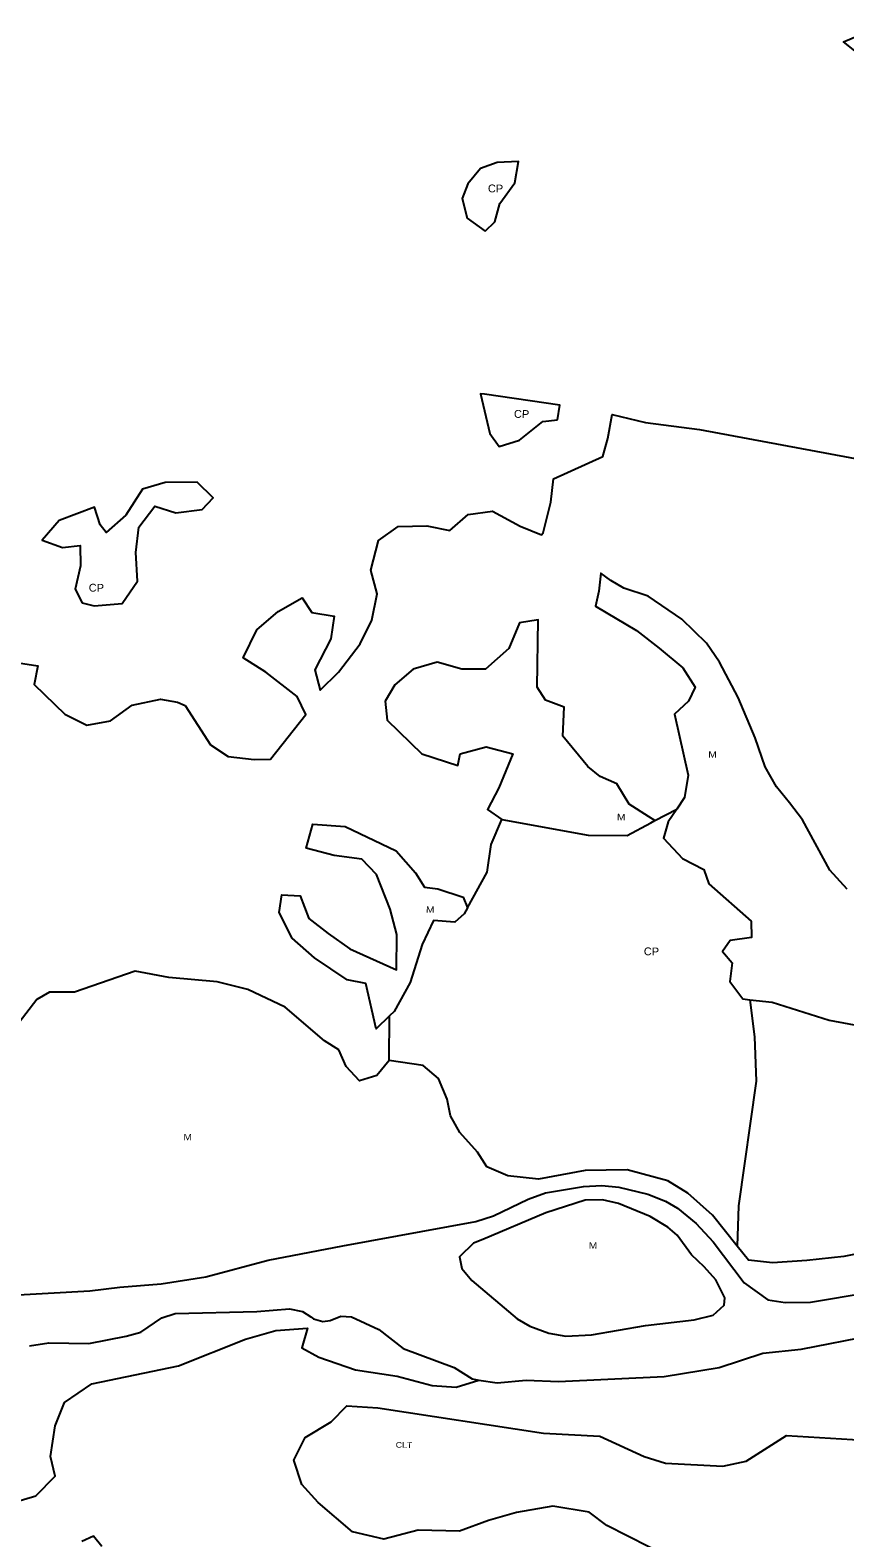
# Model space of a CAD drawing. Extents: x 713589 to 726391, y 7177764 to 7191819.
# Drawn here: x 714627 to 715293, y 7183555 to 7184788 of the extents above; entities that cross this region are included whole.
import ezdxf
from ezdxf.enums import TextEntityAlignment as Align

# ---------------------------------------------------------------- set-up
doc = ezdxf.new("R2010")
doc.units = 0
doc.header["$LTSCALE"] = 2.6
doc.layers.add('63', color=7, linetype='Continuous', lineweight=25)

msp = doc.modelspace()

# ---------------------------------------------------------------- linework, layer by layer
at = {"layer": '63'}
for p, q in [((715138.11, 7184141.59), (715156.05, 7184151.08)), ((714920.75, 7183945.47), (714921.2, 7183982.13))]:
    msp.add_line(p, q, dxfattribs=at)
for points in [[(715325.72, 7184751.48), (715292.21, 7184778.11), (715314.82, 7184787.71)], [(714570.18, 7184277.99), (714633.55, 7184268.01), (714630.56, 7184252.97), (714655.77, 7184228.68), (714673.69, 7184219.68), (714692.97, 7184223.3), (714710.6, 7184235.9), (714733.86, 7184240.84), (714747.81, 7184238.5), (714754.12, 7184235.83), (714774.66, 7184203.57), (714789.26, 7184193.91), (714810.52, 7184191.55), (714823.81, 7184191.86), (714852.77, 7184228.35), (714845.49, 7184242.98), (714819.94, 7184262.96), (714801.36, 7184274.62), (714812.69, 7184297.52), (714829.99, 7184312.44), (714849.61, 7184323.71), (714857.56, 7184311.73), (714875.83, 7184308.71), (714873.14, 7184290.11), (714860.14, 7184264.89), (714864.43, 7184248.27), (714879.41, 7184262.86), (714897.05, 7184286.09), (714906.72, 7184305.34), (714911.08, 7184326.93), (714905.79, 7184346.2), (714912.14, 7184370.45), (714928.11, 7184382.05), (714951.7, 7184382.67), (714970.3, 7184378.65), (714985.27, 7184391.92), (715005.21, 7184394.54), (715027.78, 7184382.21), (715045.23, 7184375.2), (715046.7, 7184376.87), (715046.72, 7184376.95), (715053.06, 7184401.77), (715055.05, 7184421.08), (715095.34, 7184439.15), (715099.65, 7184453.85), (715103.23, 7184473.54), (715130.31, 7184467.09), (715174.48, 7184461.37), (715348.51, 7184428.86)], [(715295.07, 7184085.69), (715281.03, 7184101.19), (715258.57, 7184142.13), (715248.02, 7184156.25), (715237.41, 7184169.1), (715228.08, 7184185.48), (715219.89, 7184209.34), (715205.99, 7184242.33), (715190.8, 7184271.2), (715180.1, 7184286.65), (715160.1, 7184306.32), (715132.56, 7184324.98), (715112.59, 7184331.72), (715102.02, 7184337.91), (715093.74, 7184343.74), (715092.14, 7184329.28), (715089.53, 7184316.92), (715122.98, 7184297.01), (715141.56, 7184282.69), (715160.8, 7184266.38), (715171.08, 7184250.75), (715165.41, 7184239.13), (715154.1, 7184228.52), (715165.31, 7184178.67), (715162.29, 7184160.4), (715156.05, 7184151.08)], [(715138.11, 7184141.59), (715132.72, 7184145.08), (715117.1, 7184155.16), (715106.83, 7184171.79), (715093.22, 7184177.79), (715083.26, 7184185.78), (715062.71, 7184210.73), (715063.74, 7184234.32), (715048.47, 7184239.99), (715041.84, 7184250.63), (715042.6, 7184305.78), (715027.31, 7184303.15), (715018.64, 7184282.23), (714999.68, 7184265.32), (714980.07, 7184265.35), (714960.15, 7184271.03), (714940.54, 7184265.42), (714925.57, 7184252.49), (714917.57, 7184239.21), (714919.21, 7184223.59), (714947.4, 7184196.3), (714976.95, 7184186.62), (714978.96, 7184196.25), (715000.23, 7184201.86), (715021.82, 7184196.18), (715010.48, 7184168.29), (715001.15, 7184150.7), (715012.79, 7184142.53)], [(714984.72, 7184070.22), (715000.82, 7184099.54), (715004.18, 7184122.13), (715012.79, 7184142.53)], [(715012.79, 7184142.53), (715083.5, 7184129.64), (715115.39, 7184129.58), (715134.6, 7184139.73), (715138.11, 7184141.59)], [(715156.05, 7184151.08), (715148.97, 7184140.49), (715144.96, 7184127.21), (715160.54, 7184110.57), (715178.14, 7184101.57), (715182.1, 7184089.94), (715216.6, 7184059.32), (715216.91, 7184046.03), (715199.64, 7184043.73), (715193.31, 7184034.77), (715201.27, 7184025.46), (715199.25, 7184010.18), (715209.85, 7183995.87), (715215.59, 7183995.22)], [(714921.2, 7183982.13), (714910.24, 7183971.45), (714901.67, 7184008.35), (714886.39, 7184011.36), (714859.84, 7184029.34), (714841.6, 7184045.65), (714831, 7184066.6), (714833.02, 7184080.88), (714847.97, 7184080.19), (714855.24, 7184061.58), (714870.84, 7184049.26), (714888.76, 7184036.94), (714926.93, 7184019.6), (714926.98, 7184048.5), (714921.7, 7184069.11), (714910.45, 7184097.7), (714898.51, 7184110.01), (714875.93, 7184113.04), (714853.01, 7184119.05), (714858.36, 7184138.65), (714884.94, 7184136.94), (714926.43, 7184116.94), (714942.35, 7184098.97), (714949.64, 7184087.33), (714960.6, 7184085.99), (714981.18, 7184078.98), (714984.72, 7184070.22)], [(714984.72, 7184070.22), (714982.03, 7184065.32), (714974.5, 7184058.72), (714956.94, 7184059.84), (714947.9, 7184040.49), (714937.88, 7184009.28), (714924.88, 7183985.72), (714921.2, 7183982.13)], [(714920.75, 7183945.47), (714910.75, 7183933.25), (714896.46, 7183928.95), (714885.52, 7183940.6), (714879.56, 7183954.23), (714867.95, 7183961.56), (714835.77, 7183989.19), (714805.23, 7184003.52), (714780.32, 7184009.88), (714740.79, 7184013.26), (714713.23, 7184018.62), (714663.7, 7184001.43), (714643.1, 7184001.46), (714632.79, 7183995.5), (714591.17, 7183941.42)], [(715215.59, 7183995.22), (715219.53, 7183964.96), (715220.8, 7183928.75), (715206.34, 7183826.78), (715205.17, 7183793.9)], [(715215.59, 7183995.22), (715233.77, 7183993.18), (715280.59, 7183978.48), (715337.38, 7183967.76)], [(715205.17, 7183793.9), (715184.98, 7183819.18), (715165.07, 7183837.15), (715148.48, 7183847.14), (715115.27, 7183856.17), (715081.05, 7183855.56), (715042.84, 7183848.65), (715017.93, 7183851.35), (715000.66, 7183858.68), (714993.04, 7183870.66), (714978.45, 7183886.63), (714970.83, 7183900.26), (714968.2, 7183913.88), (714961.25, 7183930.84), (714948.64, 7183941.49), (714920.75, 7183945.47)], [(714603.11, 7183753.23), (714676.02, 7183757.25), (714700.73, 7183760.3), (714734.55, 7183762.97), (714770.92, 7183768.59), (714821.86, 7183782.39), (714882.88, 7183794.14), (714991.77, 7183813.99), (715006.2, 7183818.7), (715034.37, 7183832.12), (715048.68, 7183837.36), (715079.74, 7183842.58), (715094.78, 7183843.31), (715108.56, 7183842.06), (715132.18, 7183836.29), (715146.72, 7183830.54), (715156.61, 7183824.94), (715171.67, 7183812.37), (715185.58, 7183797.29), (715211.12, 7183763.75), (715230.22, 7183749.9), (715244.62, 7183747.67), (715265.24, 7183747.91), (715312.49, 7183755.79)], [(715578.89, 7183808.53), (715571.34, 7183817.21), (715553.1, 7183831.19), (715531.18, 7183837.54), (715505.94, 7183841.57), (715485.66, 7183836.28), (715469.04, 7183828.67), (715434.81, 7183821.09), (715403.23, 7183808.18), (715352.72, 7183802.29), (715315.82, 7183790.06), (715292.56, 7183785.44), (715262.32, 7183782.17), (715234.08, 7183780.22), (715214.48, 7183782.25), (715205.17, 7183793.9)], [(714994.18, 7183684.37), (715009.01, 7183681.97), (715032.87, 7183684.14), (715059.17, 7183683.26), (715145.62, 7183687.13), (715190.45, 7183694.5), (715226.28, 7183706.37), (715257.48, 7183709.67), (715316.1, 7183721.09), (715388.15, 7183732.6), (715445.45, 7183745.95), (715466.3, 7183752.62), (715496.61, 7183763.15), (715524.1, 7183769.87), (715565.25, 7183775.38), (715591.61, 7183777.21)], [(714626.71, 7183712.35), (714642.73, 7183714.73), (714675.17, 7183714.3), (714705.73, 7183720.33), (714717.83, 7183723.52), (714734.84, 7183735.23), (714745.77, 7183738.86), (714812.75, 7183740.31), (714839.35, 7183742.67), (714849.98, 7183740.47), (714856.68, 7183736), (714858.9, 7183734.51), (714866.62, 7183732.31), (714872.57, 7183732.94), (714881.34, 7183736.7), (714889.98, 7183736.07), (714912.3, 7183725.75), (714932.14, 7183710.14), (714973.82, 7183694.52), (714988.67, 7183685.26), (714994.18, 7183684.37)], [(714607.18, 7183582.33), (714631.9, 7183589.79), (714647.66, 7183605.84), (714643.92, 7183621.92), (714647.72, 7183646.88), (714655.28, 7183666.02), (714677.88, 7183681.37), (714748.7, 7183695.96), (714803.46, 7183717.76), (714828.1, 7183724.9), (714854.02, 7183726.72), (714849.39, 7183710.57), (714863.29, 7183702.96), (714893.37, 7183692.65), (714927.23, 7183687.46), (714955.94, 7183679.89), (714975.44, 7183678.49), (714994.18, 7183684.37)], [(715150.33, 7183539.33), (715098.72, 7183565.41), (715084.38, 7183576.38), (715054.63, 7183581.22), (715024.86, 7183576.14), (715001.94, 7183569.68), (714978.32, 7183560.82), (714944.46, 7183561.56), (714916.4, 7183554.43), (714890.76, 7183560.28), (714862.75, 7183584.27), (714849.44, 7183599), (714842.97, 7183618.85), (714852.24, 7183637.3), (714873.47, 7183650.27), (714886.33, 7183663.25), (714911.52, 7183661.69), (715046.93, 7183640.95), (715093.1, 7183638.48), (715129.32, 7183622), (715146.76, 7183616.5), (715193.61, 7183614.02), (715212.77, 7183618.1), (715245.64, 7183638.91), (715317.46, 7183634.68)], [(714685.87, 7183548.31), (714679.04, 7183556.87), (714669.46, 7183552.44)]]:
    msp.add_lwpolyline(points, dxfattribs=at)
for points in [[(714999.27, 7184623.45), (715007.26, 7184631.08), (715011.27, 7184646.02), (715023.59, 7184662.94), (715026.44, 7184680.27), (715009, 7184679.58), (714995.37, 7184674.62), (714985.05, 7184662.01), (714980.38, 7184650.06), (714984.67, 7184634.11)], [(715058.48, 7184469.29), (715060.31, 7184481.21), (714998.79, 7184490.23), (714995.52, 7184490.5), (715002.98, 7184458), (715010.61, 7184447.36), (715027.23, 7184452.64), (715046.52, 7184467.89)], [(714705.54, 7184391.39), (714689.57, 7184377.13), (714684.6, 7184383.45), (714679.97, 7184397.74), (714651.05, 7184386.82), (714637.07, 7184370.9), (714653.67, 7184364.89), (714668.29, 7184366.53), (714668.59, 7184349.92), (714664.24, 7184330.66), (714669.87, 7184319.69), (714679.73, 7184317.2), (714702.43, 7184318.97), (714715.08, 7184337.22), (714713.79, 7184360.81), (714716.15, 7184381.4), (714729.14, 7184398.66), (714746.41, 7184393.31), (714768, 7184395.93), (714776.99, 7184405.55), (714763.72, 7184418.2), (714737.81, 7184417.91), (714719.2, 7184412.62)], [(715195.1, 7183751.54), (715187.97, 7183766.2), (715178.39, 7183776.79), (715167.82, 7183786.8), (715156.24, 7183802.84), (715148.61, 7183809.41), (715134.03, 7183818.11), (715108.33, 7183828.58), (715095.16, 7183831.74), (715081.06, 7183831.32), (715048.91, 7183821.04), (714997.5, 7183799.23), (714989.75, 7183796.3), (714978.32, 7183785.11), (714980.31, 7183775.55), (714988.28, 7183765.74), (715025.4, 7183734.38), (715035.73, 7183728.34), (715051.2, 7183722.68), (715065.1, 7183720.16), (715086.07, 7183721.25), (715130.31, 7183729.02), (715170.04, 7183733.61), (715185.57, 7183737.5), (715194.6, 7183745.61)]]:
    msp.add_lwpolyline(points, close=True, dxfattribs=at)

# ---------------------------------------------------------------- texts
for s, height, width, p in [('CP', 6.4, 1.05, (715007.71, 7184655.1)), ('CP', 6.4, 1.05, (715029.02, 7184470.79)), ('CP', 6.4, 1.05, (714681.43, 7184328.73)), ('M', 5.2, 1.2, (715185.09, 7184193.08)), ('M', 5.2, 1.2, (715110.44, 7184141.94)), ('M', 5.2, 1.2, (714954.34, 7184066.33)), ('CP', 6.4, 1.05, (715135.17, 7184031.5)), ('M', 5.2, 1.2, (714756.05, 7183880.34)), ('M', 5.2, 1.2, (715087.36, 7183791.78)), ('CLT', 4.64, 1.15, (714932.88, 7183628.98))]:
    msp.add_text(s, height=height, rotation=359.062, dxfattribs=dict(at, width=width)).set_placement(p, align=Align.CENTER)

doc.saveas('drawing.dxf')
